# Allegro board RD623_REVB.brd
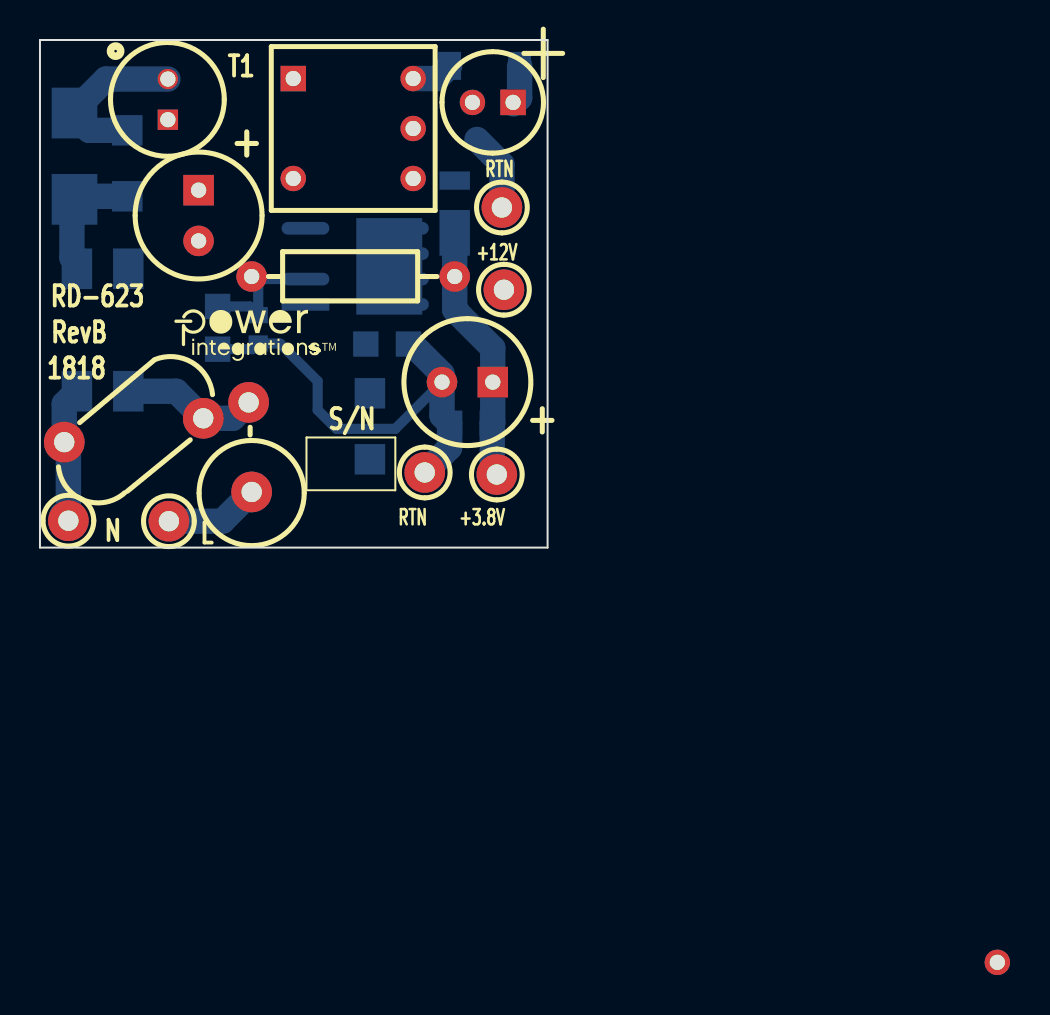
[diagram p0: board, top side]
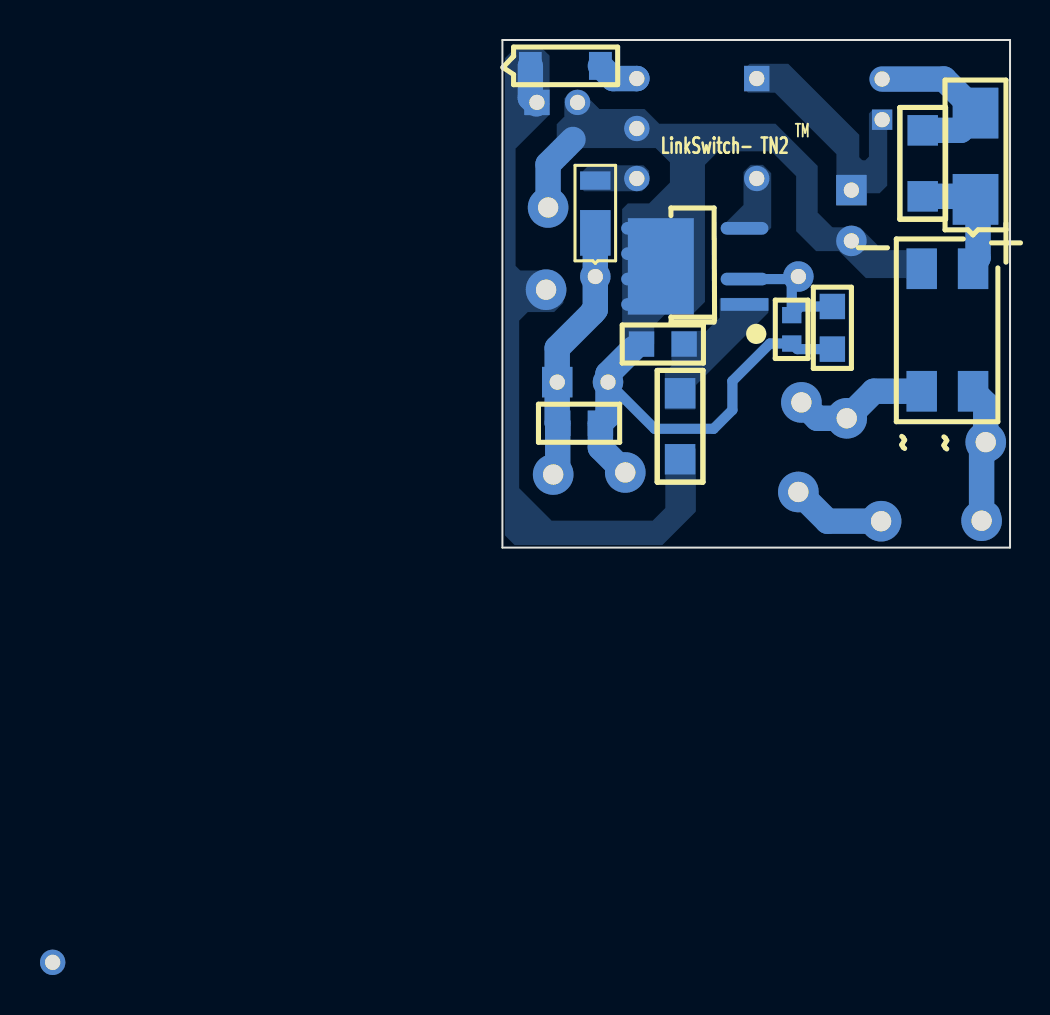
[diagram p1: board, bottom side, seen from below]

Outline 25.4 x 25.4 mm; copper layers: TOP, BOTTOM. Coordinates in mm from the lower left corner of the outline.
Outline path: 0,25.4 25.4,25.4 25.4,0 0,0 0,25.4

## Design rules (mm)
constraint set DEFAULT: min track width 0.508

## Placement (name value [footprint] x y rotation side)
BR1  B10S-G  [PISMSOIC4]  4.42 7.82 180 bottom
C1  1 uF  [PIPOLCAPCYLD250LS100030]  7.94 17.89 270 top
C3  100 nF  [PISMC0805]  16.31 10.19 0 bottom
C4  100 nF  [PISMC0805]  8.89 12.06 270 bottom
C5  56 uF  [PIPOLCAPCLYD200LS80030]  23.67 22.28 180 top
C6  220  uF  [PIPOLCAPCYLD250LS100030]  22.66 8.28 180 top
C7  10 uF  [PISMC0805]  22.63 6.22 180 bottom
D2  DA22F2100L  [PI_SM_SOD-123_12]  24 24.1 180 bottom
D3  DFLS160-7  [PISMDDFLR120012]  20.75 15.72 270 bottom
L1  2.2 mH  [PI_CHOKE_RL5480-1_D2]  6.4 21.41 90 top
NOREF  -  []  6.17 11.81 0 top
NOREF#2  -  []  -150.78 54.23 0 top
NOREF#3  -  []  0 0 0 top
NOREF#4  -  []  25.4 0 90 top
NOREF#5  -  []  -228.6 -144.78 0 top
R1  30 k  [PISMR1206]  4.37 20.88 270 bottom
R4  22.6 k  [PISMR0603]  10.92 11.63 270 bottom
R5  71.5 k  [PISMR1206]  16.51 7.72 270 bottom
R6  13 k  [PI14WRESD100LS500D030]  10.59 13.56 0 top
RF1  8.2  [PI2WRESD200LS725D040]  10.57 -1.02 90 top
RV1  275 Vac  [PIDISC350X160LS210X140040]  8.17 6.47 220 top
T1  EE8.3  [PI_BOBBIN_EE8_3_V6P]  12.67 23.47 0 top
TP1  WHT  [PITPKEYSTONE100X100]  6.45 1.32 90 top
TP2  BLK  [PITPKEYSTONE100X100]  1.42 1.35 90 top
TP3  BLUE  [PITPKEYSTONE100X100]  23.22 12.9 0 top
TP4  BLK  [PITPKEYSTONE100X100]  19.25 3.76 0 top
TP5  RED  [PITPKEYSTONE100X100]  22.86 3.66 0 top
TP6  BLK  [PITPKEYSTONE100X100]  23.11 17.02 0 top
U1  LNK3202D  [PISMSO8DNSHORT5678]  13.28 12.17 90 bottom
VR1  PTZTE2543A  [PISMDO214AC12]  1.73 17.42 90 bottom

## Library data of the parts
BR1 = DIODE BRIDGE_~~+-: alternate symbols: (pi_sm_soic4_slot)
C1 C6 = CAP POL: alternate symbols: (pipolcapcyld250ls100030h)
C3 C4 C7 = CAP NP
C5 = CAP POL
D2 = DIODE
D3 = DIODE SCHOTTKY
L1 = INDUCTOR_dot2
R1 R5 = R
R4 = R: tolerance: 1%
R6 = R: alternate symbols: (pi14wvresd100ls200d030,pi14wresd100ls400d030,pi14wresd100ls500d030)
RF1 = RF: alternate symbols: (pi2wresd200ls900d040,pi2wvresd200ls300d040,pi2wvresd200ls400d040,pi2wvresd180ls250d040,pi2wvresd180ls200d040)
RV1 = VARISTOR: alternate symbols: (pi_disc_354x220_ls220x10_040_h)
T1 = BEE8_3_6P
TP1-TP6 = TESTPOINT
U1 = LNK32XX_8C
VR1 = DIODE_ZENER

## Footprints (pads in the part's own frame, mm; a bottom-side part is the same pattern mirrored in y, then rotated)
PI2WRESD200LS725D040
  round 2.032 hole 1.016: 1(3.799,-0.025) 2(8.28,0.127)
PI14WRESD100LS500D030
  round 1.524 hole 0.762: 1(0,0) 2(10.16,0)
PI_BOBBIN_EE8_3_V6P
  rect 1.27x1.27 hole 0.762: 1(0,0)
  round 1.27 hole 0.762: 2(35.23,-44.221) 3(0,-5.001) 4(6,-5.001) 5(6,-2.499) 6(6,0)
PI_CHOKE_RL5480-1_D2
  rect 1.016x1.016 hole 0.762: 1(0,0)
  round 1.016 hole 0.762: 2(2.032,0)
PI_SM_SOD-123_12
  rect 1.143x1.397 smd: 1(0,0) 2(3.505,0)
PIDISC350X160LS210X140040
  round 2.032 hole 1.016: 1(0,0) 2(6.096,-3.556)
PIPOLCAPCLYD200LS80030
  rect 1.27x1.27 hole 0.762: 1(0,0)
  round 1.27 hole 0.762: 2(2.032,0)
PIPOLCAPCYLD250LS100030
  rect 1.524x1.524 hole 0.762: 1(0,0)
  round 1.524 hole 0.762: 2(2.54,0)
PISMC0805
  rect 1.27x1.27 smd: 1(0,0) 2(2.134,0)
PISMDDFLR120012
  rect 2.286x1.524 smd: 1(-0.025,0)
  rect 0.914x1.524 smd: 2(-2.642,0)
PISMDO214AC12
  rect 2.54x2.286 smd: 1(0,0) 2(4.318,0)
PISMR0603
  rect 0.813x0.965 smd: 1(0,0) 2(1.422,0)
PISMR1206
  rect 1.524x1.524 smd: 1(0,0) 2(3.302,0)
PISMSO8DNSHORT5678
  rect 0.635x2.388 smd: 1(0,0)
  oval 0.635x2.388 smd: 2(1.27,0) 4(3.81,0) 5(3.81,4.978) 6(2.54,4.978) 7(1.27,4.978) 8(0,4.978)
PISMSOIC4
  rect 1.524x2.032 smd: 1(0,0) 2(2.571,0) 3(2.571,6.129) 4(0,6.129)
PITPKEYSTONE100X100
  round 2.032 hole 1.016: 1(0,0)

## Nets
SOURCE: BR1.4 C1.2 C3.2 C4.2 C5.2 C6.2 C7.2 R4.2 T1.5 TP4.1 TP6.1 U1.5(S) U1.6 U1.7 U1.8
N25701: C1.1 L1.1 T1.1
N25747: T1.3 U1.4
N25978: C4.1 R4.1 R6.1 U1.2
N46358: D3.2 T1.4
N138558: C3.1 R5.1 U1.1
N149717: L1.2 R1.1 VR1.2
N156669: BR1.2 RV1.2 TP2.1
N156684: BR1.1 RF1.2 RV1.1
N157774: D2.2 T1.6
N157829: C5.1 D2.1 R5.2 TP3.1
N159322: C6.1 C7.1 D3.1 R6.2 TP5.1
N165873: BR1.3 R1.2 VR1.1
N172947: RF1.1 TP1.1

Pads without a net: T1 2

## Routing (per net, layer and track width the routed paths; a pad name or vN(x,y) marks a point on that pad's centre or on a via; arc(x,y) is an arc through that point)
SOURCE: length 26.2
  BOTTOM w0.508: C4.2 10.64,9.93 R4.2 12.01,10.21 13.89,8.33 13.89,6.88 14.83,5.94 17.78,5.94 C6.2
  BOTTOM w1.27: TP6.1 23.11,19.18 21.87,20.42 ; TP4.1 20.5,5 C7.2 20.12,6.6 C6.2 20.12,8.69 18.85,9.96
N25978: length 6.8
  BOTTOM w0.508: C4.1 10.49,12.06 R4.1 10.92,13.23 10.72,13.44 ; R6.1 10.72,13.44 ; 10.72,13.44 U1.2
N149717: length 8.5
  BOTTOM w1.27: L1.2 3.3,23.44 1.73,21.87 VR1.2 1.73,21.62 2.46,20.88 R1.1
N156669: length 7.3
  BOTTOM w1.27: BR1.2 1.22,7.19 RV1.2 1.42,5.07 TP2.1 1.12,1.65
N156684: length 6.9
  BOTTOM w1.27: RF1.2 9.65,6.47 RV1.1 6.82,7.82 BR1.1
N157774: length 2.1
  BOTTOM w1.27: T1.6 19.86,23.47 D2.2
N157829: length 2
  BOTTOM w1.27: D2.1 24,22.5 23.7,22.2
N159322: length 13
  BOTTOM w1.27: D3.1 R6.2 20.75,11.91 20.88,11.79 20.88,11.76 22.66,9.98 C6.1 22.66,6.25 C7.1 22.63,3.89 TP5.1
N165873: length 6.4
  BOTTOM w1.27: R1.2 1.75,17.58 1.73,17.55 VR1.1 1.6,17.3 1.6,14.51 1.85,14.26 BR1.3
N172947: length 4.7
  BOTTOM w1.27: TP1.1 9.13,1.32 RF1.1

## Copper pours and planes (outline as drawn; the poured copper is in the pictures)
SOURCE on BOTTOM (solid shape): 19.13,11.66 15.82,11.66 15.82,16.48 19.13,16.48
SOURCE on BOTTOM: 17.73,19.99 17.02,19.28 17.02,18.26 18.06,17.22 19.13,17.22 19.41,16.94 19.41,9.8 19.35,9.75 18.24,9.75 17.81,10.19 17.81,11.13 17.2,11.73 15.82,11.73 15.27,12.29 15.27,19.15 14.59,19.82 11.94,19.82 10.7,18.59 10.7,15.83 9.7,14.83 8.56,14.83 7.21,13.49 3.78,13.49 3.78,14.78 3.89,14.88 6.38,14.88 7.52,16.03 8.89,16.03 9.63,16.76 9.63,19.1 11.73,21.21 17.55,21.21 18.29,21.95 20.55,21.95 21.39,22.78 22,22.78 22.3,22.48 22.3,21.56 22.68,21.18 22.68,19.99
N25701 on BOTTOM: 6.15,21.89 6.15,18.11 6.53,17.73 7.16,17.73 7.16,17.27 7.29,17.14 8.43,17.14 8.69,17.4 8.69,19.68 11.76,22.76 13.11,22.76 13.26,22.91 13.26,23.98 13.03,24.21 11.1,24.21 7.54,20.65 7.54,19.53 7.39,19.38 7.24,19.38 7.06,19.56 7.06,21.72 6.88,21.89
N25747 on BOTTOM: 12.37,19.15 11.95,18.73 11.95,16 12.2,15.75 14.17,15.75 14.3,15.88 14.3,16.18 13.34,17.14 13.34,18.8 12.98,19.15
N46358 on BOTTOM: 18.06,18.85 18.06,18.19 18.41,17.83 21.31,17.83 21.44,17.96 21.44,18.77 21.08,19.13 18.34,19.13
N138558 on BOTTOM: 16.94,10.85 15.19,10.85 14.53,11.51 14.53,12.45 14.48,12.5 12.12,12.5 12.09,12.47 12.09,11.76 15.72,8.13 15.72,6.96 15.77,6.91 17.25,6.91 17.27,6.93 17.27,8.76 16.94,9.09
N157829 on BOTTOM: 24.74,14.1 24.51,13.87 22.86,13.87 22.35,13.36 22.35,12.24 22.81,11.79 24.13,11.79 24.56,11.35 24.56,2.97 22.94,1.35 17.88,1.35 17.25,1.98 17.25,4.85 17.14,4.95 15.72,4.95 15.72,1.8 17.4,0.13 24.79,0.13 25.27,0.61 25.27,24.49 24.84,24.92 23.34,24.92 23.04,24.61 23.04,21.67 24.74,19.96

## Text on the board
Ref Des/Silkscreen Bottom: TM | LinkSwitch- TN2
Ref Des/Silkscreen Top: RTN | +3.8V | +12V | 1818 | RD-623 | RevB | N | L | S/N
PAGE_OUTLINE: 14.  FAB HOUSE LOGO,DATE CODE TO BE IN SILK SCREEN ONLY.DO NOT USE COPPER. | 13.  MATERIAL FR4 COPPER 2oz THICKNESS 0.039" | PLEASE DELETE THIS PIN
User.5: FIGURE | FINISHED_SIZE | 30.0 | 40.0 | DRILL CHART: TOP to BOTTOM | ALL UNITS ARE IN MILS | PLATED | QTY | 16 | 10
